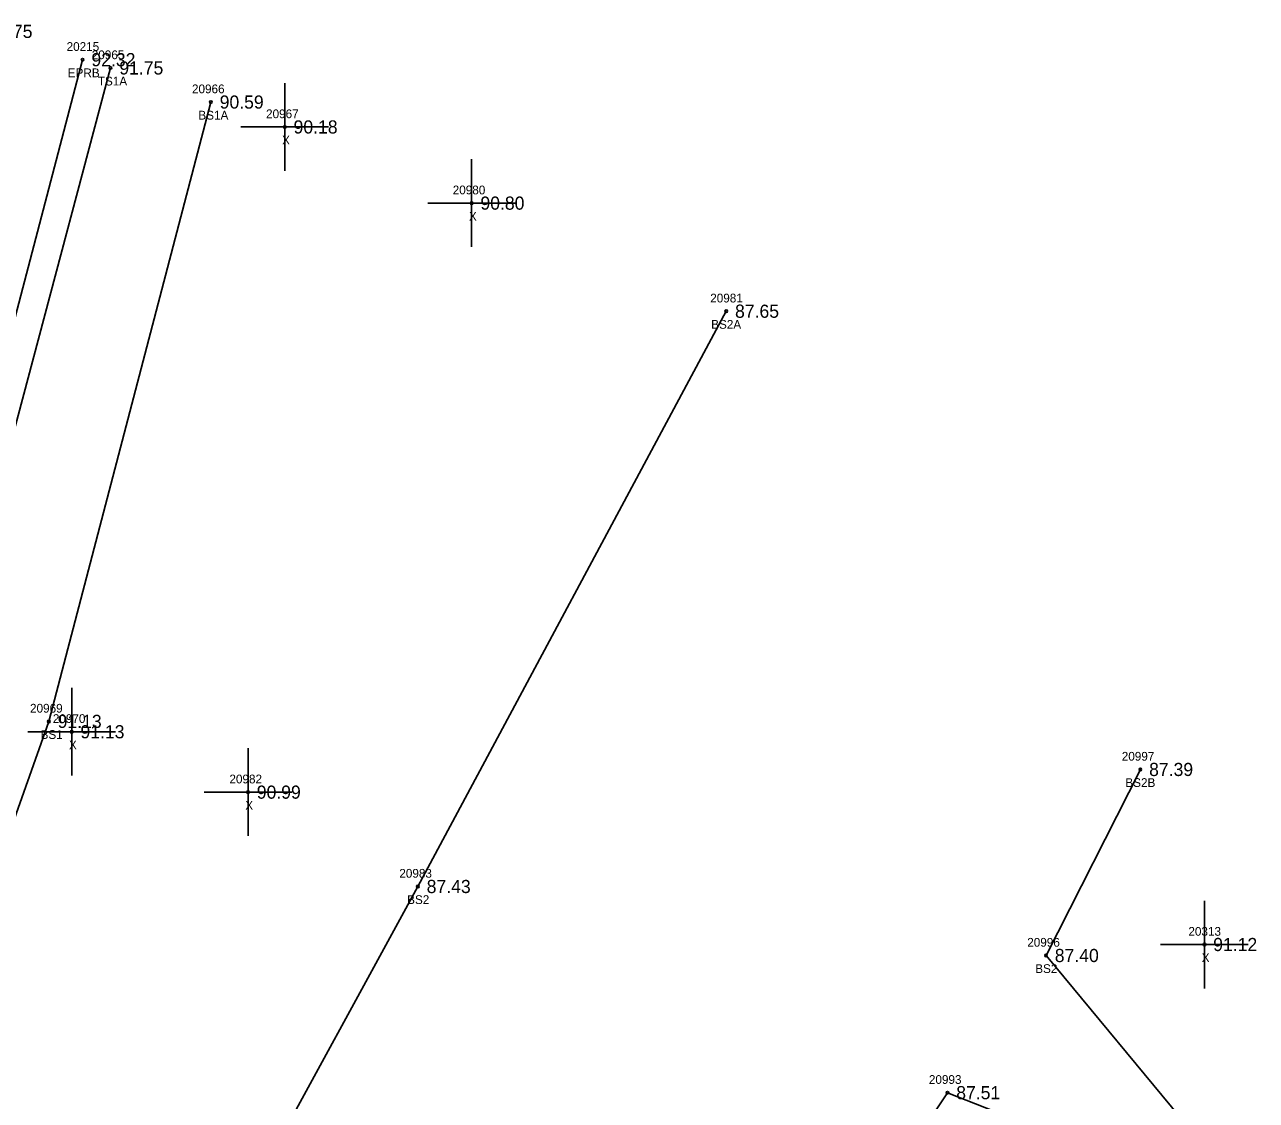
# Model space of a CAD drawing. Extents: x 2530197 to 2532051, y 935230 to 936631.
# Drawn here: x 2531837.5 to 2531978, y 936460.9 to 936583.6 of the extents above; entities that cross this region are included whole.
import ezdxf

# ---------------------------------------------------------------- set-up
doc = ezdxf.new("R2010")
doc.units = 0
for name, color, linetype in [('RD_DTM_BkLn2', 7, 'Continuous'), ('RD_DTM_BkLn_txCode', 7, 'Continuous'), ('RD_EX_Misc', 7, 'Continuous'), ('RD_EX_Misc_txCode', 7, 'Continuous'), ('RD_EX_Road', 7, 'Continuous'), ('RD_EX_Road_txCode', 7, 'Continuous'), ('RD_EX_TX_Misc_ELEV', 7, 'Continuous'), ('RD_EX_TX_Road_ELEV', 7, 'Continuous'), ('RD_HC_Survey_ELEV', 7, 'Continuous'), ('RD_SMD_Locator', 7, 'Continuous')]:
    doc.layers.add(name, color=color, linetype=linetype)

msp = doc.modelspace()

# ---------------------------------------------------------------- linework, layer by layer
at = {"layer": 'RD_DTM_BkLn2'}
for points in [[(2531847.31, 936578.71), (2531828.5, 936507.99), (2531807.07, 936433.9), (2531793.16, 936383.74), (2531787.14, 936359.39), (2531794.14, 936352.47)], [(2531858.76, 936574.82), (2531840.28, 936504.17), (2531814.37, 936431.07), (2531798.77, 936381.67), (2531794.1, 936358.42), (2531794.14, 936352.47)], [(2531917.54, 936550.96), (2531882.37, 936485.34), (2531845.03, 936416.88), (2531807.92, 936350.36), (2531800.08, 936331.1), (2531815.28, 936323.11), (2531842.04, 936353.56), (2531870.4, 936350.41), (2531903.53, 936402.83), (2531942.77, 936461.82), (2531965.7, 936452.8), (2531970.35, 936457.79), (2531954.01, 936477.47), (2531964.77, 936498.69)]]:
    msp.add_lwpolyline(points, dxfattribs=at)
at = {"layer": 'RD_EX_Misc'}
for p, q in [((2531867.19, 936566.98), (2531867.19, 936576.98)), ((2531862.19, 936571.98), (2531872.19, 936571.98)), ((2531888.5, 936558.29), (2531888.5, 936568.29)), ((2531883.5, 936563.29), (2531893.5, 936563.29)), ((2531842.88, 936497.99), (2531842.88, 936507.99)), ((2531837.88, 936502.99), (2531847.88, 936502.99)), ((2531862.99, 936491.1), (2531862.99, 936501.1)), ((2531857.99, 936496.1), (2531867.99, 936496.1)), ((2531972.08, 936473.72), (2531972.08, 936483.72)), ((2531967.08, 936478.72), (2531977.08, 936478.72))]:
    msp.add_line(p, q, dxfattribs=at)
at = {"layer": 'RD_EX_Road'}
msp.add_lwpolyline([(2531180.82, 935982), (2531220.82, 936004.21), (2531303.54, 936053.39), (2531388.75, 936103.71), (2531472.27, 936152.98), (2531554.79, 936201.9), (2531638.11, 936250.92), (2531683.19, 936278.28), (2531730.37, 936304.55), (2531771.5, 936341.26), (2531788.67, 936375.53), (2531805.57, 936434.84), (2531825.53, 936508.74), (2531844.13, 936579.65)], dxfattribs=at)
at = {"layer": 'RD_SMD_Locator'}
for centre in [(2531844.13, 936579.65), (2531847.31, 936578.71), (2531858.76, 936574.82), (2531867.19, 936571.98), (2531888.5, 936563.29), (2531917.54, 936550.96), (2531840.28, 936504.17), (2531842.88, 936502.99), (2531964.77, 936498.69), (2531862.99, 936496.1), (2531882.37, 936485.34), (2531972.08, 936478.72), (2531954.01, 936477.47), (2531942.77, 936461.82)]:
    msp.add_circle(centre, 0.15, dxfattribs=at)

# ---------------------------------------------------------------- texts
at = {"layer": 'RD_DTM_BkLn_txCode'}
for s, p in [('20965', (2531845.17, 936579.71)), ('TS1A', (2531845.86, 936576.71)), ('20966', (2531856.6, 936575.82)), ('BS1A', (2531857.33, 936572.82)), ('20981', (2531915.71, 936551.96)), ('BS2A', (2531915.82, 936548.96)), ('20969', (2531838.13, 936505.17)), ('BS1', (2531839.33, 936502.17)), ('20997', (2531962.65, 936499.69)), ('BS2B', (2531963.06, 936496.69)), ('20983', (2531880.25, 936486.34)), ('BS2', (2531881.14, 936483.34)), ('20996', (2531951.87, 936478.47)), ('BS2', (2531952.78, 936475.47)), ('20993', (2531940.65, 936462.82))]:
    msp.add_text(s, height=1, dxfattribs=at).set_placement(p)
at = {"layer": 'RD_EX_Misc_txCode'}
for s, p in [('20967', (2531865.05, 936572.98)), ('X', (2531866.88, 936569.98)), ('20980', (2531886.34, 936564.29)), ('X', (2531888.19, 936561.29)), ('20970', (2531840.73, 936503.99)), ('X', (2531842.57, 936500.99)), ('20982', (2531860.87, 936497.1)), ('X', (2531862.68, 936494.1)), ('20313', (2531970.25, 936479.72)), ('X', (2531971.77, 936476.72))]:
    msp.add_text(s, height=1, dxfattribs=at).set_placement(p)
at = {"layer": 'RD_EX_Road_txCode'}
for s, p in [('20215', (2531842.3, 936580.65)), ('EPRB', (2531842.43, 936577.65))]:
    msp.add_text(s, height=1, dxfattribs=at).set_placement(p)
at = {"layer": 'RD_EX_TX_Misc_ELEV'}
for s, p in [('91.75', (2531848.31, 936577.96)), ('90.59', (2531859.76, 936574.07)), ('90.18', (2531868.19, 936571.23)), ('90.80', (2531889.5, 936562.54)), ('87.65', (2531918.54, 936550.21)), ('91.13', (2531841.28, 936503.42)), ('91.13', (2531843.88, 936502.24)), ('87.39', (2531965.77, 936497.94)), ('90.99', (2531863.99, 936495.35)), ('87.43', (2531883.37, 936484.59)), ('91.12', (2531973.08, 936477.97)), ('87.40', (2531955.01, 936476.72)), ('87.51', (2531943.77, 936461.07))]:
    msp.add_text(s, height=1.5, dxfattribs=at).set_placement(p)
at = {"layer": 'RD_EX_TX_Road_ELEV'}
msp.add_text('92.32', height=1.5, dxfattribs=at).set_placement((2531845.13, 936578.9))
at = {"layer": 'RD_HC_Survey_ELEV'}
msp.add_text('92.75', height=1.5, dxfattribs=at).set_placement((2531833.39, 936582.13))

doc.saveas('drawing.dxf')
